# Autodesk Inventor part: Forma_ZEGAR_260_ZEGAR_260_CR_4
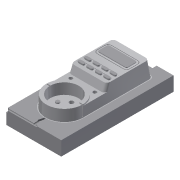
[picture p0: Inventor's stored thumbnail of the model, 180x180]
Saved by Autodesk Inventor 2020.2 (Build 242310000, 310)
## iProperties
Created: 2015-01
Part Number: Forma_ZEGAR_260_ZEGAR_260_CR_4
Material: Ogólny
Document SubType Name: Modeling
Designer: F.Stasiak
Density: 1 g/cm^3
Appearance: Domyślna
Catalog Web Link: www.expertbooks.pl
Manager: www.cadconsulting.pl
Company: Fabian Stasiak CAD Consulting
Author: F.Stasiak
Subject: Zbiór ćwiczeń. Autodesk Inventor 2020. Kurs Professional
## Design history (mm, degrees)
node "Forma_ZEGAR_260_ZEGAR_260_CR_Base"
feature "Rzeźbienie3"
feature "Bryła5::Forma_ZEGAR_260_ZEGAR_260_CR_Base"
tag "Bryła wyprowadzona1"
node "Bryła1"
feature "Forma_ZEGAR_260_ZEGAR_260_CR_Base_Bodies"
feature "Powierzchnia3"
body "Srf3"
